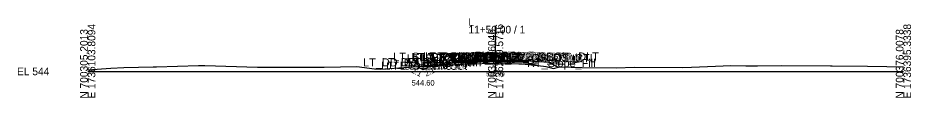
# Model space of a CAD drawing. Extents: x -26 to 697, y -10 to 2642.
# Drawn here: x -25.7 to 302.8, y 590.3 to 619.6 of the extents above; entities that cross this region are included whole.
import ezdxf

# ---------------------------------------------------------------- set-up
doc = ezdxf.new("R2010")
doc.units = 0
for name, color, linetype in [('Default', 7, 'Continuous'), ('Exist Cross Section Cell', 7, 'Continuous'), ('Exist XS Center Line Elevation Label', 7, 'Continuous'), ('Exist XS Ground Line', 7, 'Continuous'), ('Prop CMT Ditch DDE', 7, 'Continuous'), ('Prop CMT Pvmt Course 1', 7, 'Continuous'), ('Prop CMT Pvmt Course 2', 7, 'Continuous'), ('Prop CMT Pvmt Surface', 7, 'Continuous'), ('Prop CMT Pvmt Surface Shoulder', 7, 'Continuous'), ('Prop CMT Shld Paved Course 1', 7, 'Continuous'), ('Prop CMT Shld Paved Course 2', 7, 'Continuous'), ('Prop CMT Slope Grass', 7, 'Continuous'), ('Prop CMT Subgrade Earthwork', 7, 'Continuous'), ('Prop XS Ditch Slope Text', 7, 'Continuous'), ('Prop XS Ditch Standard Text', 7, 'Continuous'), ('Prop XS SE Text', 7, 'Continuous'), ('Prop XS Side Slope Text', 7, 'Continuous')]:
    doc.layers.add(name, color=color, linetype=linetype)

msp = doc.modelspace()

# ---------------------------------------------------------------- linework, layer by layer
at = {"layer": 'Exist Cross Section Cell'}
for p, q in [((150, 600), (150, 616.8)), ((0, 600), (150, 600)), ((150, 600), (300, 600))]:
    msp.add_line(p, q, dxfattribs=at)
at = {"layer": 'Exist XS Ground Line'}
msp.add_lwpolyline([(0, 600.54), (8.55, 601.2), (13.25, 601.51), (24.04, 601.71), (24.89, 601.72), (25.35, 601.74), (40.71, 602.2), (43.03, 602.2), (62.43, 601.59), (66.59, 601.57), (84.06, 601.61), (86.96, 601.58), (98.93, 601.86), (105.43, 601.02), (107.7, 600.84), (109.23, 600.95), (123.09, 601.99), (128.34, 601.85), (128.72, 601.92), (131.94, 602.4), (135.64, 602.54), (140.34, 602.82), (149.73, 602.99), (150.26, 602.98), (159.83, 602.84), (167.62, 601.92), (168.51, 601.81), (171.35, 601.12), (173.14, 601.61), (173.71, 601.75), (181.91, 601.48), (194.36, 601.33), (201.14, 601.54), (218.62, 601.47), (222.02, 601.62), (230.88, 601.98), (236.51, 602.22), (242.04, 602.11), (246.29, 602.08), (255.17, 602.22), (273.22, 602.01), (273.82, 602.01), (286.74, 601.99), (293.89, 601.83), (300, 601.7)], dxfattribs=at)
at = {"layer": 'Prop CMT Ditch DDE'}
for points in [[(123.4, 600.6), (120.94, 601.83)], [(129, 601.96), (126, 601.9), (123.4, 600.6)], [(123.4, 600.6), (123.4, 600.6)]]:
    msp.add_lwpolyline(points, dxfattribs=at)
at = {"layer": 'Prop CMT Pvmt Course 1'}
for points in [[(150, 604.31), (139, 604.09)], [(139, 603.88), (150, 604.1)], [(139, 604.09), (139, 603.88)], [(150, 604.1), (150, 604.31)], [(150, 604.31), (161, 604.09)], [(150, 604.1), (150, 604.31)], [(161, 603.88), (150, 604.1)], [(161, 604.09), (161, 603.88)]]:
    msp.add_lwpolyline(points, dxfattribs=at)
msp.add_lwpolyline([(150, 604.1), (150, 604.2), (150, 604.2), (150, 604.1)], close=True, dxfattribs=at)
msp.add_lwpolyline([(150, 604.1), (150, 604.2), (150, 604.2), (150, 604.1)], close=True, dxfattribs=at)
at = {"layer": 'Prop CMT Pvmt Course 2'}
for points in [[(150, 604.1), (139, 603.88)], [(139, 603.88), (139, 603.42)], [(139, 603.42), (150, 603.64)], [(150, 603.64), (150, 604.1)], [(150, 603.64), (150, 604.1)], [(150, 604.1), (161, 603.88)], [(161, 603.42), (150, 603.64)], [(161, 603.88), (161, 603.42)]]:
    msp.add_lwpolyline(points, dxfattribs=at)
at = {"layer": 'Prop CMT Pvmt Surface'}
for points in [[(150, 604.31), (139, 604.09)], [(150, 604.31), (161, 604.09)]]:
    msp.add_lwpolyline(points, dxfattribs=at)
at = {"layer": 'Prop CMT Pvmt Surface Shoulder'}
for points in [[(139, 604.09), (135.66, 604.02)], [(161, 604.09), (161.01, 604.08)]]:
    msp.add_lwpolyline(points, dxfattribs=at)
at = {"layer": 'Prop CMT Shld Paved Course 1'}
for points in [[(139, 604.09), (135.66, 604.02), (135.45, 603.81)], [(135.45, 603.81), (139, 603.88)], [(139, 603.88), (139, 604.09)], [(161, 604.09), (161.01, 604.08), (161.22, 603.87)], [(161, 603.88), (161, 604.09)], [(161.22, 603.87), (161, 603.88)]]:
    msp.add_lwpolyline(points, dxfattribs=at)
at = {"layer": 'Prop CMT Shld Paved Course 2'}
for points in [[(139, 603.88), (135.45, 603.81), (135.44, 603.81), (134.97, 603.34)], [(134.97, 603.34), (139, 603.42)], [(139, 603.42), (139, 603.88)], [(161, 603.88), (161.22, 603.87), (161.23, 603.87), (161.7, 603.41)], [(161, 603.42), (161, 603.88)], [(161.7, 603.41), (161, 603.42)]]:
    msp.add_lwpolyline(points, dxfattribs=at)
at = {"layer": 'Prop CMT Slope Grass'}
for points in [[(135.66, 604.02), (132.63, 603.78), (129, 601.96)], [(161.01, 604.08), (169.42, 603.41), (173.07, 601.59)]]:
    msp.add_lwpolyline(points, dxfattribs=at)
at = {"layer": 'Prop CMT Subgrade Earthwork'}
for points in [[(134.97, 603.34), (134.4, 603.92)], [(139, 603.42), (134.97, 603.34)], [(150, 603.64), (139, 603.42)], [(150, 603.64), (161, 603.42)], [(161, 603.42), (161.7, 603.41)], [(161.7, 603.41), (162.28, 603.98)]]:
    msp.add_lwpolyline(points, dxfattribs=at)

# ---------------------------------------------------------------- texts
at = {"layer": 'Default'}
for s, height, p in [('LT_DD_Boundary Out', 3, (101.28, 601.83)), ('LT_DD_Boundary In', 3, (108.18, 601.9)), ('LT_Sub_Trench_Out_DLT', 3, (112.35, 603.92)), ('LT_Sub_Trench_Out', 3, (117.3, 603.34)), ('LT_Slope_Fill', 3, (117.71, 601.96)), ('LT_GS_OS_CTL', 3, (119.02, 603.78)), ('LT_PS2_Shelf_Out', 3, (119.41, 603.81)), ('LT_PS2_OEOP', 3, (122.81, 603.81)), ('LT_PS1_OEOP', 3, (123.38, 604.02)), ('LT_PV2_OEOT', 3, (126.24, 603.88)), ('LT_Sub_OEOT', 3, (126.31, 603.42)), ('LT_PV1_OEOT', 3, (126.6, 604.09)), ('RT_PV2_OEEOP', 3, (136, 604.1)), ('RT_Sub_OEEOP', 3, (136.07, 603.64)), ('LT_PV2_OEEOP', 3, (136.18, 604.1)), ('LT_Sub_OEEOP', 3, (136.25, 603.64)), ('RT_PV1_OEEOP', 3, (136.36, 604.2)), ('LT_PV1_OEEOP', 3, (136.54, 604.2)), ('RT_PV2_IEEOP', 3, (137.14, 604.1)), ('LT_PV2_IEEOP', 3, (137.32, 604.1)), ('RT_PV1_IEEOP', 3, (137.5, 604.2)), ('LT_PV1_IEEOP', 3, (137.68, 604.2)), ('RT_Sub_Trench_Out_DLT', 3, (140.05, 603.98)), ('PV2_PGL', 3, (142.05, 604.1)), ('PV1_PGL', 3, (142.41, 604.31)), ('RT_Sub_Trench_Out', 3, (143.85, 603.41)), ('RT_PS2_Shelf_Out', 3, (145.03, 603.87)), ('RT_PV2_OEOT', 3, (148.06, 603.88)), ('RT_Sub_OEOT', 3, (148.13, 603.42)), ('RT_PS2_OEOP', 3, (148.4, 603.87)), ('RT_PV1_OEOT', 3, (148.42, 604.09)), ('RT_PS1_OEOP', 3, (148.55, 604.08)), ('RT_GS_OS_CTL', 3, (155.63, 603.41)), ('RT_Slope_Fill', 3, (161.6, 601.59)), ('LT_DD_Base Out', 3, (107.9, 600.6)), ('LT_DD_Base In', 3, (109.73, 600.6)), ('-', 0.0001, (0, 600))]:
    msp.add_text(s, height=height, dxfattribs=at).set_placement(p)
at = {"layer": 'Exist Cross Section Cell'}
for s, p in [('L', (140, 616.8)), ('11+50.00 / 1', (140, 614)), ('EL 544', (-26, 598.6))]:
    msp.add_text(s, height=2.8, dxfattribs=at).set_placement(p)
for s, p in [('N 700305.2013', (0, 590)), ('E 1736103.8094', (2.8, 590)), ('N 700340.6046', (150, 590)), ('E 1736249.5716', (152.8, 590)), ('N 700376.0078', (300, 590)), ('E 1736395.3338', (302.8, 590))]:
    msp.add_text(s, height=2.8, rotation=90, dxfattribs=at).set_placement(p)
at = {"layer": 'Exist XS Center Line Elevation Label'}
msp.add_text('546.99', height=1.6, dxfattribs=at).set_placement((146.59, 598.19))
at = {"layer": 'Prop XS Ditch Slope Text'}
for rotation, p in [(333.4349, (118.82, 599.71)), (26.5651, (124.51, 598.08))]:
    msp.add_text('2:1', height=2, rotation=rotation, dxfattribs=at).set_placement(p)
at = {"layer": 'Prop XS Ditch Standard Text'}
msp.add_text('544.60', height=2, dxfattribs=at).set_placement((119.13, 594.8))
at = {"layer": 'Prop XS SE Text'}
for rotation, p in [(1.1458, (140.98, 605.12)), (358.8542, (152.02, 605.26))]:
    msp.add_text('0.020', height=2, rotation=rotation, dxfattribs=at).set_placement(p)
at = {"layer": 'Prop XS Side Slope Text'}
for rotation, p in [(26.5651, (129.06, 602.83)), (333.4349, (170.16, 603.88))]:
    msp.add_text('2:1', height=2, rotation=rotation, dxfattribs=at).set_placement(p)

doc.saveas('drawing.dxf')
